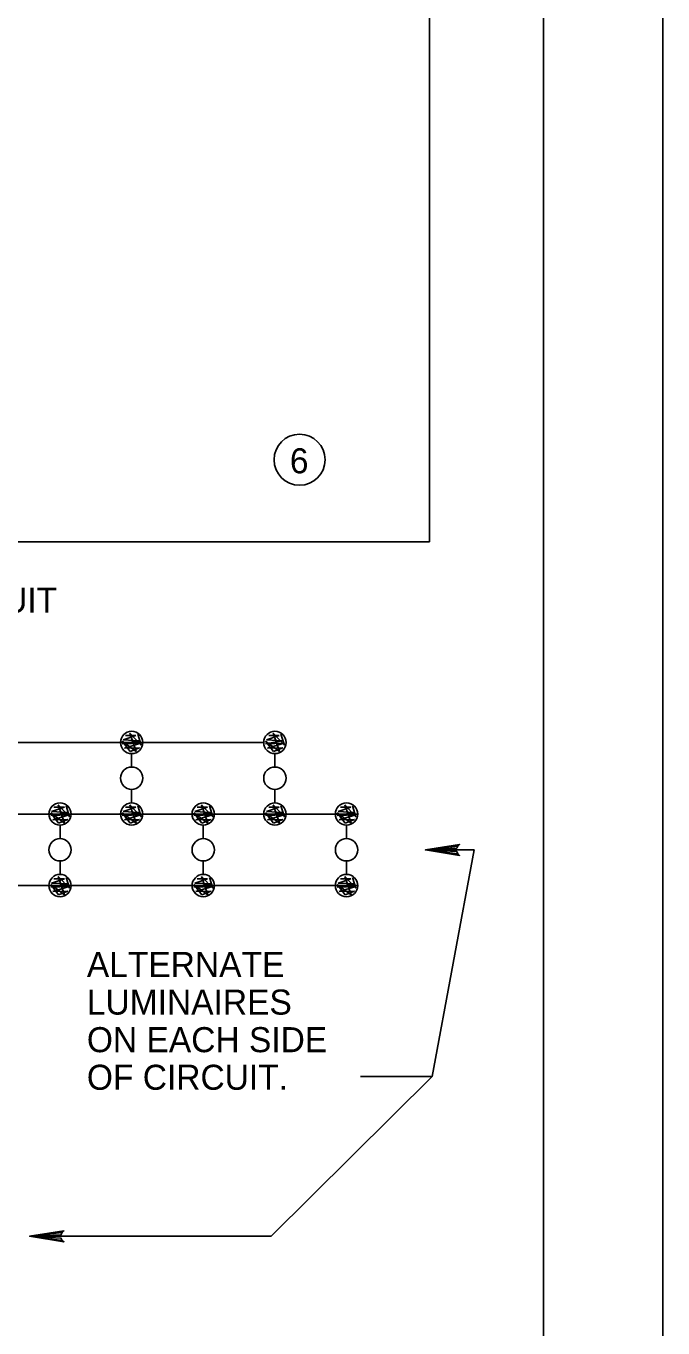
# Model space of a CAD drawing. Extents: x 638448 to 639352, y 297825 to 299013.
# Drawn here: x 639203.3 to 639288.7, y 298647.6 to 298822.2 of the extents above; entities that cross this region are included whole.
import ezdxf

# ---------------------------------------------------------------- set-up
doc = ezdxf.new("R2010")
doc.units = 0
for name, color, linetype in [('1', 7, 'Continuous'), ('2', 7, 'Continuous'), ('3', 7, 'Continuous'), ('PLT-BNDY', 7, 'Continuous')]:
    doc.layers.add(name, color=color, linetype=linetype)

msp = doc.modelspace()

# ---------------------------------------------------------------- linework, layer by layer
at = {"layer": '1'}
msp.add_lwpolyline([(639272.65, 298434.29), (639272.65, 298998.29), (638486.65, 298998.29), (638486.65, 298434.29), (639272.65, 298434.29), (639272.65, 298460.65), (639072.65, 298460.65), (639072.65, 298525.33), (639272.65, 298525.33), (639272.65, 298554.29), (639072.65, 298554.29), (639072.65, 298434.29), (639151.45, 298434.29), (639151.45, 298460.65), (639151.45, 298434.29), (639228.45, 298434.29), (639228.45, 298460.65), (639228.45, 298448.33), (639272.65, 298448.33)], dxfattribs=at)
at = {"layer": '2'}
for p, q in [((639257.36, 298753.02), (639257.36, 298916.22)), ((639089.66, 298753.02), (639257.36, 298753.02)), ((639218.04, 298727.06), (639216.32, 298726.47)), ((639216.63, 298727.06), (639218.04, 298727.06)), ((639218.07, 298724.91), (639217.22, 298727.37)), ((639217.22, 298727.37), (639218.72, 298725.77)), ((639218.72, 298725.77), (639218.27, 298727.22)), ((639237.24, 298727.06), (639235.52, 298726.47)), ((639235.83, 298727.06), (639237.24, 298727.06)), ((639237.27, 298724.91), (639236.42, 298727.37)), ((639236.42, 298727.37), (639237.92, 298725.77)), ((639237.92, 298725.77), (639237.47, 298727.22)), ((639170.7, 298726.13), (639235.16, 298726.13)), ((639218.43, 298726.35), (639216.21, 298725.93)), ((639217.28, 298724.91), (639216.21, 298726.28)), ((639216.21, 298726.28), (639218.07, 298724.91)), ((639216.21, 298725.93), (639218.69, 298726.02)), ((639216.32, 298726.47), (639218.43, 298726.35)), ((639218.69, 298726.02), (639216.48, 298725.35)), ((639216.48, 298725.35), (639218.52, 298725.39)), ((639218.52, 298725.39), (639217.28, 298724.91)), ((639217.46, 298726.13), (639217.46, 298726.13)), ((639217.46, 298726.13), (639217.46, 298726.13)), ((639237.63, 298726.35), (639235.41, 298725.93)), ((639236.48, 298724.91), (639235.41, 298726.28)), ((639235.41, 298726.28), (639237.27, 298724.91)), ((639235.41, 298725.93), (639237.89, 298726.02)), ((639235.52, 298726.47), (639237.63, 298726.35)), ((639237.89, 298726.02), (639235.68, 298725.35)), ((639235.68, 298725.35), (639237.72, 298725.39)), ((639237.72, 298725.39), (639236.48, 298724.91)), ((639236.66, 298726.13), (639236.66, 298726.13)), ((639236.66, 298726.13), (639236.66, 298726.13)), ((639217.46, 298724.63), (639217.46, 298722.83)), ((639236.66, 298724.63), (639236.66, 298722.83)), ((639217.46, 298719.83), (639217.46, 298718.03)), ((639236.66, 298719.83), (639236.66, 298718.03)), ((639158.7, 298716.53), (639247.76, 298716.53)), ((639208.83, 298716.75), (639206.61, 298716.33)), ((639207.68, 298715.31), (639206.61, 298716.68)), ((639206.61, 298716.68), (639208.47, 298715.31)), ((639208.44, 298717.46), (639206.72, 298716.87)), ((639206.72, 298716.87), (639208.83, 298716.75)), ((639207.03, 298717.46), (639208.44, 298717.46)), ((639208.47, 298715.31), (639207.62, 298717.77)), ((639207.62, 298717.77), (639209.12, 298716.17)), ((639207.86, 298716.53), (639207.86, 298716.53)), ((639207.86, 298716.53), (639207.86, 298716.53)), ((639207.86, 298716.53), (639207.86, 298716.53)), ((639207.86, 298716.53), (639207.86, 298716.53)), ((639209.12, 298716.17), (639208.67, 298717.62)), ((639218.43, 298716.75), (639216.21, 298716.33)), ((639217.28, 298715.31), (639216.21, 298716.68)), ((639216.21, 298716.68), (639218.07, 298715.31)), ((639218.04, 298717.46), (639216.32, 298716.87)), ((639216.32, 298716.87), (639218.43, 298716.75)), ((639216.63, 298717.46), (639218.04, 298717.46)), ((639218.07, 298715.31), (639217.22, 298717.77)), ((639217.22, 298717.77), (639218.72, 298716.17)), ((639217.42, 298716.62), (639217.42, 298716.62)), ((639217.46, 298716.53), (639217.46, 298716.53)), ((639217.46, 298716.53), (639217.46, 298716.53)), ((639217.46, 298716.53), (639217.46, 298716.53)), ((639217.46, 298716.53), (639217.46, 298716.53)), ((639218.72, 298716.17), (639218.27, 298717.62)), ((639228.03, 298716.75), (639225.81, 298716.33)), ((639226.88, 298715.31), (639225.81, 298716.68)), ((639225.81, 298716.68), (639227.67, 298715.31)), ((639227.64, 298717.46), (639225.92, 298716.87)), ((639225.92, 298716.87), (639228.03, 298716.75)), ((639226.23, 298717.46), (639227.64, 298717.46)), ((639227.67, 298715.31), (639226.82, 298717.77)), ((639226.82, 298717.77), (639228.32, 298716.17)), ((639227.06, 298716.53), (639227.06, 298716.53)), ((639227.06, 298716.53), (639227.06, 298716.53)), ((639227.06, 298716.53), (639227.06, 298716.53)), ((639227.06, 298716.53), (639227.06, 298716.53)), ((639227.06, 298716.53), (639227.06, 298716.53)), ((639228.32, 298716.17), (639227.87, 298717.62)), ((639237.63, 298716.75), (639235.41, 298716.33)), ((639236.48, 298715.31), (639235.41, 298716.68)), ((639235.41, 298716.68), (639237.27, 298715.31)), ((639237.24, 298717.46), (639235.52, 298716.87)), ((639235.52, 298716.87), (639237.63, 298716.75)), ((639235.83, 298717.46), (639237.24, 298717.46)), ((639237.27, 298715.31), (639236.42, 298717.77)), ((639236.42, 298717.77), (639237.92, 298716.17)), ((639236.62, 298716.62), (639236.62, 298716.62)), ((639236.66, 298716.53), (639236.66, 298716.53)), ((639236.66, 298716.53), (639236.66, 298716.53)), ((639236.66, 298716.53), (639236.66, 298716.53)), ((639236.66, 298716.53), (639236.66, 298716.53)), ((639236.66, 298716.53), (639236.66, 298716.53)), ((639237.92, 298716.17), (639237.47, 298717.62)), ((639247.23, 298716.75), (639245.01, 298716.33)), ((639246.08, 298715.31), (639245.01, 298716.68)), ((639245.01, 298716.68), (639246.87, 298715.31)), ((639246.84, 298717.46), (639245.12, 298716.87)), ((639245.12, 298716.87), (639247.23, 298716.75)), ((639245.43, 298717.46), (639246.84, 298717.46)), ((639246.87, 298715.31), (639246.02, 298717.77)), ((639246.02, 298717.77), (639247.52, 298716.17)), ((639246.26, 298716.53), (639246.26, 298716.53)), ((639246.26, 298716.53), (639246.26, 298716.53)), ((639246.26, 298716.53), (639246.26, 298716.53)), ((639246.26, 298716.53), (639246.26, 298716.53)), ((639246.26, 298716.53), (639246.26, 298716.53)), ((639246.26, 298716.53), (639246.26, 298716.53)), ((639247.52, 298716.17), (639247.07, 298717.62)), ((639206.61, 298716.33), (639209.09, 298716.42)), ((639209.09, 298716.42), (639206.88, 298715.75)), ((639206.88, 298715.75), (639208.92, 298715.79)), ((639208.92, 298715.79), (639207.68, 298715.31)), ((639207.86, 298715.03), (639207.86, 298713.23)), ((639216.21, 298716.33), (639218.69, 298716.42)), ((639218.69, 298716.42), (639216.48, 298715.75)), ((639216.48, 298715.75), (639218.52, 298715.79)), ((639218.52, 298715.79), (639217.28, 298715.31)), ((639225.81, 298716.33), (639228.29, 298716.42)), ((639228.29, 298716.42), (639226.08, 298715.75)), ((639226.08, 298715.75), (639228.12, 298715.79)), ((639228.12, 298715.79), (639226.88, 298715.31)), ((639227.06, 298715.03), (639227.06, 298713.23)), ((639235.41, 298716.33), (639237.89, 298716.42)), ((639237.89, 298716.42), (639235.68, 298715.75)), ((639235.68, 298715.75), (639237.72, 298715.79)), ((639237.72, 298715.79), (639236.48, 298715.31)), ((639245.01, 298716.33), (639247.49, 298716.42)), ((639247.49, 298716.42), (639245.28, 298715.75)), ((639245.28, 298715.75), (639247.32, 298715.79)), ((639247.32, 298715.79), (639246.08, 298715.31)), ((639246.26, 298715.03), (639246.26, 298713.23)), ((639263.36, 298711.72), (639256.83, 298711.72)), ((639257.74, 298681.33), (639263.36, 298711.72)), ((639207.86, 298710.23), (639207.86, 298708.43)), ((639227.06, 298710.23), (639227.06, 298708.43)), ((639246.26, 298710.23), (639246.26, 298708.43)), ((639208.44, 298707.86), (639206.72, 298707.27)), ((639207.03, 298707.86), (639208.44, 298707.86)), ((639208.47, 298705.71), (639207.62, 298708.17)), ((639207.62, 298708.17), (639209.12, 298706.57)), ((639209.12, 298706.57), (639208.67, 298708.02)), ((639227.64, 298707.86), (639225.92, 298707.27)), ((639226.23, 298707.86), (639227.64, 298707.86)), ((639227.67, 298705.71), (639226.82, 298708.17)), ((639226.82, 298708.17), (639228.32, 298706.57)), ((639228.32, 298706.57), (639227.87, 298708.02)), ((639246.84, 298707.86), (639245.12, 298707.27)), ((639245.43, 298707.86), (639246.84, 298707.86)), ((639246.87, 298705.71), (639246.02, 298708.17)), ((639246.02, 298708.17), (639247.52, 298706.57)), ((639247.52, 298706.57), (639247.07, 298708.02)), ((639164.7, 298706.93), (639247.76, 298706.93)), ((639208.83, 298707.15), (639206.61, 298706.73)), ((639207.68, 298705.71), (639206.61, 298707.08)), ((639206.61, 298707.08), (639208.47, 298705.71)), ((639206.61, 298706.73), (639209.09, 298706.82)), ((639206.72, 298707.27), (639208.83, 298707.15)), ((639209.09, 298706.82), (639206.88, 298706.15)), ((639206.88, 298706.15), (639208.92, 298706.19)), ((639208.92, 298706.19), (639207.68, 298705.71)), ((639207.82, 298707.02), (639207.82, 298707.02)), ((639207.86, 298706.93), (639207.86, 298706.93)), ((639207.86, 298706.93), (639207.86, 298706.93)), ((639207.86, 298706.93), (639207.86, 298706.93)), ((639207.86, 298706.93), (639207.86, 298706.93)), ((639207.86, 298706.93), (639207.86, 298706.93)), ((639228.03, 298707.15), (639225.81, 298706.73)), ((639226.88, 298705.71), (639225.81, 298707.08)), ((639225.81, 298707.08), (639227.67, 298705.71)), ((639225.81, 298706.73), (639228.29, 298706.82)), ((639225.92, 298707.27), (639228.03, 298707.15)), ((639228.29, 298706.82), (639226.08, 298706.15)), ((639226.08, 298706.15), (639228.12, 298706.19)), ((639228.12, 298706.19), (639226.88, 298705.71)), ((639227.02, 298707.02), (639227.02, 298707.02)), ((639227.06, 298706.93), (639227.06, 298706.93)), ((639227.06, 298706.93), (639227.06, 298706.93)), ((639227.06, 298706.93), (639227.06, 298706.93)), ((639227.06, 298706.93), (639227.06, 298706.93)), ((639227.06, 298706.93), (639227.06, 298706.93)), ((639247.23, 298707.15), (639245.01, 298706.73)), ((639246.08, 298705.71), (639245.01, 298707.08)), ((639245.01, 298707.08), (639246.87, 298705.71)), ((639245.01, 298706.73), (639247.49, 298706.82)), ((639245.12, 298707.27), (639247.23, 298707.15)), ((639247.49, 298706.82), (639245.28, 298706.15)), ((639245.28, 298706.15), (639247.32, 298706.19)), ((639247.32, 298706.19), (639246.08, 298705.71)), ((639246.22, 298707.02), (639246.22, 298707.02)), ((639246.26, 298706.93), (639246.26, 298706.93)), ((639246.26, 298706.93), (639246.26, 298706.93)), ((639246.26, 298706.93), (639246.26, 298706.93)), ((639246.26, 298706.93), (639246.26, 298706.93)), ((639246.26, 298706.93), (639246.26, 298706.93)), ((639236.15, 298659.9), (639257.74, 298681.33)), ((639257.74, 298681.33), (639248.14, 298681.33)), ((639236.15, 298659.9), (639203.79, 298659.9))]:
    msp.add_line(p, q, dxfattribs=at)
for points in [[(639261.19, 298711.18), (639261.02, 298711.49), (639256.83, 298711.72), (639261.19, 298711.18), (639261.41, 298710.98), (639256.83, 298711.72), (639261.02, 298711.93), (639261.17, 298712.24), (639256.83, 298711.72), (639261.41, 298712.45), (639261.17, 298712.24)], [(639208.15, 298659.35), (639207.99, 298659.67), (639203.79, 298659.9), (639208.15, 298659.35), (639208.38, 298659.16), (639203.79, 298659.9), (639207.99, 298660.11), (639208.14, 298660.42), (639203.79, 298659.9), (639208.38, 298660.63), (639208.14, 298660.42)]]:
    msp.add_lwpolyline(points, dxfattribs=at)
for centre in [(639217.46, 298726.13), (639236.66, 298726.13), (639217.46, 298721.33), (639236.66, 298721.33), (639207.86, 298716.53), (639217.46, 298716.53), (639227.06, 298716.53), (639236.66, 298716.53), (639246.26, 298716.53), (639207.86, 298711.73), (639227.06, 298711.73), (639246.26, 298711.73), (639207.86, 298706.93), (639227.06, 298706.93), (639246.26, 298706.93)]:
    msp.add_circle(centre, 1.5, dxfattribs=at)
at = {"layer": '3'}
msp.add_circle((639239.96, 298764.04), 3.42, dxfattribs=at)
at = {"layer": 'PLT-BNDY'}
msp.add_lwpolyline([(638447.65, 299013.29), (639288.65, 299013.29), (639288.65, 298419.29), (638447.65, 298419.29)], close=True, dxfattribs=at)

# ---------------------------------------------------------------- texts
at = {"layer": '3'}
for s, p in [('6', (639238.66, 298762.22)), ('CONDUIT', (639187.01, 298743.52)), ('ALTERNATE', (639211.46, 298694.67)), ('LUMINAIRES', (639211.46, 298689.63)), ('ON EACH SIDE', (639211.46, 298684.59)), ('OF CIRCUIT.', (639211.46, 298679.55))]:
    msp.add_text(s, height=3.36, dxfattribs=at).set_placement(p)

doc.saveas('drawing.dxf')
